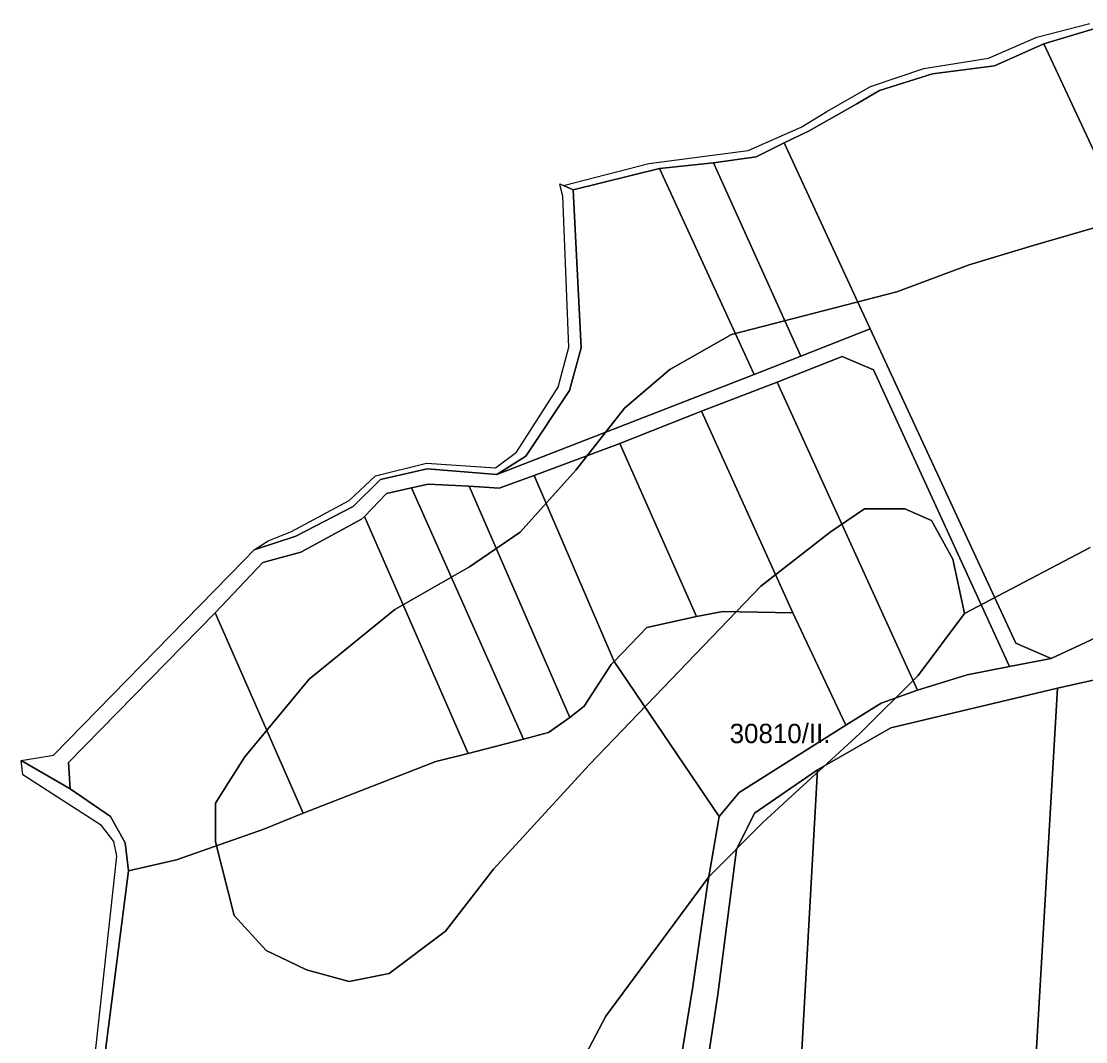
# Model space of a CAD drawing. Extents: x -541351 to -537540, y -1162694 to -1159725.
# Drawn here: x -541350.8 to -541076, y -1161202.6 to -1160939.1 of the extents above; entities that cross this region are included whole.
import ezdxf

# ---------------------------------------------------------------- set-up
doc = ezdxf.new("R2010")
doc.units = 0
for name, color, linetype in [('95560013', 7, 'Continuous'), ('95630013', 7, 'Continuous'), ('95640013', 7, 'Continuous'), ('95660013', 7, 'Continuous')]:
    doc.layers.add(name, color=color, linetype=linetype)

msp = doc.modelspace()

# ---------------------------------------------------------------- linework, layer by layer
at = {"layer": '95560013'}
for points in [[(-541033.05, -1161060.07), (-541086.85, -1160944.98), (-541073.08, -1160940.82), (-541069.85, -1160939.12), (-541019.98, -1161046.9), (-541028.84, -1161055.79)], [(-541131.65, -1161018.53), (-541153.86, -1160970.54), (-541147.43, -1160967.41), (-541135.11, -1160960.45), (-541129.26, -1160956.98), (-541115.54, -1160952.68), (-541099.59, -1160950.61), (-541086.85, -1160944.98), (-541033.05, -1161060.07), (-541054.13, -1161080.42), (-541071.61, -1161096.64), (-541073.5, -1161098.28), (-541084.97, -1161103.63), (-541094.05, -1161099.67)], [(-541131.65, -1161018.53), (-541149.55, -1161025.6), (-541172.1, -1160975.69), (-541161.06, -1160974.14), (-541153.86, -1160970.54)], [(-541161.61, -1161030.33), (-541228.07, -1161056.14), (-541220.56, -1161051.38), (-541209.3, -1161034.42), (-541206.24, -1161023.44), (-541208.35, -1160982.65), (-541186.08, -1160977.09)], [(-541149.55, -1161025.6), (-541161.61, -1161030.33), (-541186.08, -1160977.09), (-541172.1, -1160975.69)], [(-541084.97, -1161103.63), (-541095.72, -1161105.75), (-541130.8, -1161029.11), (-541138.9, -1161025.67), (-541155.69, -1161032.31), (-541175.2, -1161039.79), (-541196.32, -1161048.14), (-541218.36, -1161056.41), (-541227.45, -1161059.67), (-541235.18, -1161059.16), (-541245.76, -1161058.61), (-541250.1, -1161059.59), (-541256.5, -1161061), (-541262.2, -1161066.96), (-541262.98, -1161067.67), (-541278.61, -1161076.19), (-541288.44, -1161078.89), (-541300.77, -1161091.81), (-541338.59, -1161130.49), (-541338.21, -1161137.28), (-541350.79, -1161129.97), (-541342.47, -1161128.62), (-541293.38, -1161078.37), (-541290.67, -1161075.6), (-541279.94, -1161072.09), (-541265.15, -1161064.43), (-541258.08, -1161057.42), (-541245.99, -1161054.69), (-541228.07, -1161056.14), (-541161.61, -1161030.33), (-541149.55, -1161025.6), (-541131.65, -1161018.53), (-541094.05, -1161099.67)], [(-541155.69, -1161032.31), (-541138.9, -1161025.67), (-541130.8, -1161029.11), (-541095.72, -1161105.75), (-541106.61, -1161107.88), (-541119.44, -1161111.8)], [(-541137.93, -1161120.85), (-541151.67, -1161091.86), (-541175.2, -1161039.79), (-541155.69, -1161032.31), (-541119.44, -1161111.8), (-541128.8, -1161115.18)], [(-541151.67, -1161091.86), (-541169.67, -1161091.55), (-541176.5, -1161092.8), (-541196.32, -1161048.14), (-541175.2, -1161039.79)], [(-541196.32, -1161048.14), (-541176.5, -1161092.8), (-541189.29, -1161095.66), (-541197.74, -1161104.39), (-541218.36, -1161056.41)], [(-541197.74, -1161104.39), (-541198.51, -1161105.18), (-541205.51, -1161115.95), (-541209.2, -1161118.86), (-541235.18, -1161059.16), (-541227.45, -1161059.67), (-541218.36, -1161056.41)], [(-541262.2, -1161066.96), (-541256.5, -1161061), (-541250.1, -1161059.59), (-541221.13, -1161124.45), (-541235.46, -1161128.14)], [(-541250.1, -1161059.59), (-541245.76, -1161058.61), (-541235.18, -1161059.16), (-541209.2, -1161118.86), (-541214.69, -1161122.79), (-541221.13, -1161124.45)], [(-541235.46, -1161128.14), (-541243.8, -1161130.23), (-541278.05, -1161143.55), (-541300.77, -1161091.81), (-541288.44, -1161078.89), (-541278.61, -1161076.19), (-541262.98, -1161067.67), (-541262.2, -1161066.96)], [(-541338.21, -1161137.28), (-541338.59, -1161130.49), (-541300.77, -1161091.81), (-541278.05, -1161143.55), (-541288.2, -1161147.67), (-541310.74, -1161155.62), (-541323.15, -1161158.46), (-541323.96, -1161151.21), (-541327.73, -1161144.42)], [(-541176.5, -1161092.8), (-541169.67, -1161091.55), (-541151.67, -1161091.86), (-541137.93, -1161120.85), (-541165.46, -1161138.22), (-541170.61, -1161144.41), (-541197.74, -1161104.39), (-541189.29, -1161095.66)], [(-541091.62, -1161326.12), (-541095.8, -1161325.34), (-541083.35, -1161111.3), (-541073.3, -1161109.03), (-541054.64, -1161091.86), (-541068.49, -1161330.02)], [(-541145.22, -1161132.35), (-541126.35, -1161121.54), (-541083.35, -1161111.3), (-541095.8, -1161325.34), (-541125.26, -1161320.58), (-541155.46, -1161315.61)], [(-541170.97, -1161190.37), (-541166.19, -1161152.97), (-541161.55, -1161143.55), (-541145.22, -1161132.35), (-541155.46, -1161315.61), (-541172.43, -1161312.81), (-541177.3, -1161306.69), (-541179.83, -1161273.84), (-541175.46, -1161219.82)]]:
    msp.add_lwpolyline(points, close=True, dxfattribs=at)
msp.add_lwpolyline([(-541330.42, -1161215.55), (-541323.15, -1161158.46), (-541310.74, -1161155.62), (-541288.2, -1161147.67), (-541278.05, -1161143.55), (-541243.8, -1161130.23), (-541235.46, -1161128.14), (-541221.13, -1161124.45), (-541214.69, -1161122.79), (-541209.2, -1161118.86), (-541205.51, -1161115.95), (-541198.51, -1161105.18), (-541197.74, -1161104.39), (-541170.61, -1161144.41), (-541173.66, -1161161.97), (-541177.48, -1161188.33), (-541182.21, -1161217.36)], dxfattribs=at)
at = {"layer": '95630013'}
msp.add_lwpolyline([(-541073.08, -1160940.82), (-541086.85, -1160944.98), (-541099.59, -1160950.61), (-541115.54, -1160952.68), (-541129.26, -1160956.98), (-541135.11, -1160960.45), (-541147.43, -1160967.41), (-541153.86, -1160970.54), (-541161.06, -1160974.14), (-541172.1, -1160975.69), (-541186.08, -1160977.09), (-541208.35, -1160982.65), (-541210.84, -1160981.54), (-541188.83, -1160975.83), (-541163.17, -1160972.48), (-541149.48, -1160966.42), (-541142.81, -1160962.39), (-541131.61, -1160955.96), (-541117.84, -1160951.35), (-541101.16, -1160948.65), (-541088.68, -1160943.22), (-541074.96, -1160939.7)], dxfattribs=at)
msp.add_lwpolyline([(-541265.15, -1161064.43), (-541279.94, -1161072.09), (-541290.67, -1161075.6), (-541287.06, -1161073.27), (-541281.01, -1161070.85), (-541266.14, -1161062.85), (-541259.37, -1161056.48), (-541246.23, -1161053.24), (-541228.36, -1161054.44), (-541223, -1161050.33), (-541212.21, -1161033.59), (-541209.46, -1161023.23), (-541211, -1160984.28), (-541211.57, -1160981.98), (-541211.78, -1160981.11), (-541210.84, -1160981.54), (-541208.35, -1160982.65), (-541206.24, -1161023.44), (-541209.3, -1161034.42), (-541220.56, -1161051.38), (-541228.07, -1161056.14), (-541245.99, -1161054.69), (-541258.08, -1161057.42)], close=True, dxfattribs=at)
at = {"layer": '95640013'}
for points in [[(-541182.21, -1161217.36), (-541177.48, -1161188.33), (-541173.66, -1161161.97), (-541170.61, -1161144.41), (-541165.46, -1161138.22), (-541137.93, -1161120.85), (-541128.8, -1161115.18), (-541119.44, -1161111.8), (-541106.61, -1161107.88), (-541095.72, -1161105.75), (-541084.97, -1161103.63), (-541073.5, -1161098.28)], [(-541073.3, -1161109.03), (-541083.35, -1161111.3), (-541126.35, -1161121.54), (-541145.22, -1161132.35), (-541161.55, -1161143.55), (-541166.19, -1161152.97), (-541170.97, -1161190.37), (-541175.46, -1161219.82)], [(-541333.01, -1161217.8), (-541326.12, -1161154.72), (-541326.93, -1161150.91), (-541330.08, -1161146.8), (-541350.43, -1161133.7), (-541350.79, -1161129.97), (-541338.21, -1161137.28), (-541327.73, -1161144.42), (-541323.96, -1161151.21), (-541323.15, -1161158.46), (-541330.42, -1161215.55)]]:
    msp.add_lwpolyline(points, dxfattribs=at)
at = {"layer": '95660013'}
for points in [[(-541333.01, -1161217.8), (-541326.12, -1161154.72), (-541326.93, -1161150.91), (-541330.08, -1161146.8), (-541350.43, -1161133.7), (-541350.79, -1161129.97), (-541342.47, -1161128.62), (-541293.38, -1161078.37), (-541290.67, -1161075.6), (-541287.06, -1161073.27), (-541281.01, -1161070.85), (-541266.14, -1161062.85), (-541259.37, -1161056.48), (-541246.23, -1161053.24), (-541228.36, -1161054.44), (-541223, -1161050.33), (-541212.21, -1161033.59), (-541209.46, -1161023.23), (-541211, -1160984.28), (-541211.57, -1160981.98), (-541211.78, -1160981.11), (-541210.84, -1160981.54), (-541188.83, -1160975.83), (-541163.17, -1160972.48), (-541149.48, -1160966.42), (-541142.81, -1160962.39), (-541131.61, -1160955.96), (-541117.84, -1160951.35), (-541101.16, -1160948.65), (-541088.68, -1160943.22), (-541074.96, -1160939.7)], [(-541062, -1160989), (-541089.62, -1160997), (-541106.12, -1161002), (-541124.81, -1161009), (-541167.5, -1161020), (-541183.37, -1161029), (-541195.12, -1161039), (-541207.62, -1161055), (-541222, -1161071), (-541235.12, -1161080), (-541254.37, -1161091), (-541276.5, -1161109), (-541293.12, -1161129), (-541297.33, -1161135.67), (-541300.69, -1161141), (-541300.69, -1161151), (-541295.81, -1161170), (-541287.62, -1161179), (-541281.83, -1161181.78), (-541277.19, -1161184), (-541266.19, -1161187), (-541255.81, -1161185), (-541241.31, -1161174), (-541228.87, -1161158), (-541204.12, -1161131), (-541159.87, -1161085), (-541142, -1161071), (-541133.12, -1161065), (-541122.69, -1161065), (-541115.81, -1161068), (-541110.31, -1161078), (-541107.31, -1161092), (-541119.31, -1161108), (-541134.31, -1161123), (-541159.37, -1161146), (-541173.31, -1161160), (-541199.87, -1161196), (-541209.37, -1161214)], [(-541074.87, -1161075), (-541107.31, -1161092), (-541110.31, -1161078), (-541115.81, -1161068), (-541122.69, -1161065), (-541133.12, -1161065), (-541142, -1161071), (-541159.87, -1161085), (-541204.12, -1161131), (-541228.87, -1161158), (-541241.31, -1161174), (-541255.81, -1161185), (-541266.19, -1161187), (-541277.19, -1161184), (-541281.83, -1161181.78), (-541287.62, -1161179), (-541295.81, -1161170), (-541300.69, -1161151), (-541300.69, -1161141), (-541297.33, -1161135.67), (-541293.12, -1161129), (-541276.5, -1161109), (-541254.37, -1161091), (-541235.12, -1161080), (-541222, -1161071), (-541207.62, -1161055), (-541195.12, -1161039), (-541183.37, -1161029), (-541167.5, -1161020), (-541124.81, -1161009), (-541106.12, -1161002), (-541089.62, -1160997), (-541062, -1160989)], [(-541209.37, -1161214), (-541199.87, -1161196), (-541173.31, -1161160), (-541159.37, -1161146), (-541134.31, -1161123), (-541119.31, -1161108), (-541107.31, -1161092), (-541074.87, -1161075)]]:
    msp.add_lwpolyline(points, dxfattribs=at)

# ---------------------------------------------------------------- texts
msp.add_text('30810/II.', height=5, rotation=360, dxfattribs=at).set_placement((-541167.93, -1161125.5))

doc.saveas('drawing.dxf')
